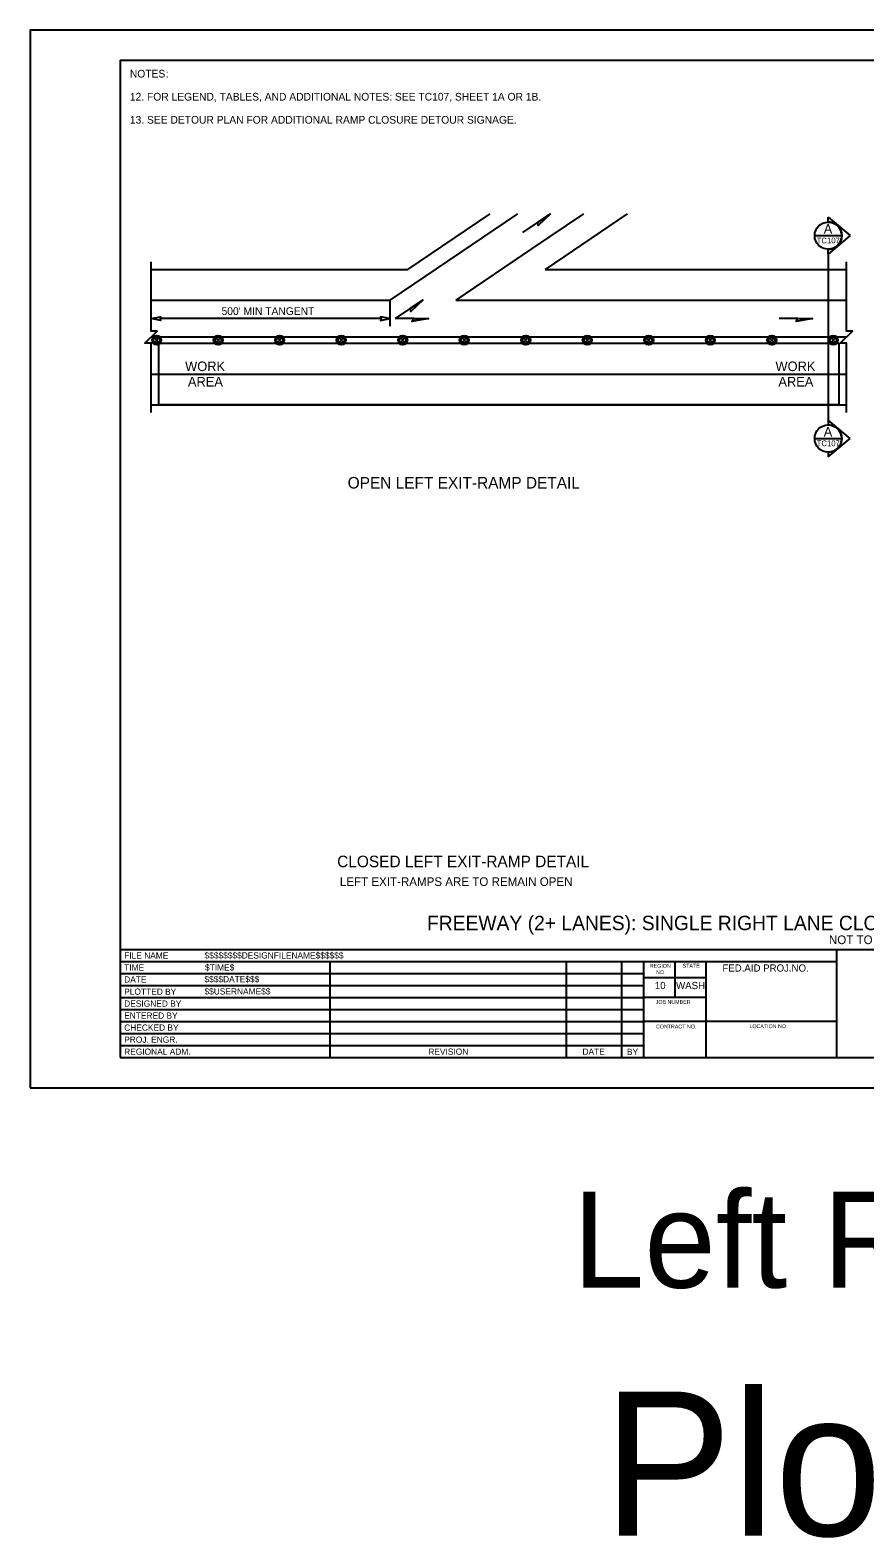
# Model space of a CAD drawing. Extents: x 99999 to 100116, y 99995 to 100013.
# Drawn here: x 100079.06 to 100087.75, y 99995.01 to 100010.69 of the extents above; entities that cross this region are included whole.
import ezdxf

# ---------------------------------------------------------------- set-up
doc = ezdxf.new("R2010")
doc.units = 0
for name, color, linetype in [('RD_MK_LineEdgeYellow', 7, 'Continuous'), ('RD_MK_LineLane', 7, 'Continuous'), ('SH_DE_DetailHeading1Text', 7, 'Continuous'), ('SH_DE_DetailHeading2Text', 7, 'Continuous'), ('SH_GI_GeneralNotesBodyText', 7, 'Continuous'), ('SH_GI_PlotLimits', 7, 'Continuous'), ('SH_GI_SheetBorder', 7, 'Continuous'), ('SH_GI_SheetLocationText', 7, 'Continuous'), ('SH_GI_SheetTextInCells', 7, 'Continuous'), ('SH_GI_TitleBlockText', 7, 'Continuous'), ('SH_TI_WZSectionCut', 7, 'Continuous'), ('TR_WZ_TrafficSafetyDrum', 7, 'Continuous'), ('TR_WZ_WorkAreaLabel', 7, 'Continuous'), ('TR_WZ_WorkZoneDetails', 7, 'Continuous'), ('TR_WZ_WorkZoneTextCurrent', 7, 'Continuous')]:
    doc.layers.add(name, color=color, linetype=linetype)

msp = doc.modelspace()

# ---------------------------------------------------------------- linework, layer by layer
at = {"layer": 'RD_MK_LineEdgeYellow'}
for p, q in [((100084.133, 100008.778), (100082.806, 100007.879)), ((100080.32, 100007.879), (100082.806, 100007.879)), ((100084.421, 100007.879), (100087.555, 100007.879)), ((100080.32, 100007.111), (100087.555, 100007.111))]:
    msp.add_line(p, q, dxfattribs=at)
at = {"layer": 'RD_MK_LineLane'}
msp.add_lwpolyline([(100087.555, 100007.495), (100080.32, 100007.495)], dxfattribs=at)
at = {"layer": 'SH_GI_PlotLimits'}
msp.add_lwpolyline([(100079.062, 99999.687), (100096.062, 99999.687), (100096.062, 100010.687), (100079.062, 100010.687)], close=True, dxfattribs=at)
at = {"layer": 'SH_GI_SheetBorder'}
for p, q in [((100080, 100010.375), (100080, 100000)), ((100080, 100010.375), (100095.75, 100010.375)), ((100080, 100001.126), (100095.75, 100001.126)), ((100087.457, 100000), (100087.457, 100001.126)), ((100080, 100001.001), (100087.457, 100001.001)), ((100082.179, 100001.001), (100082.179, 100000)), ((100084.641, 100001.001), (100084.641, 100000)), ((100085.216, 100001.001), (100085.216, 100000)), ((100085.445, 100001.001), (100085.445, 100000)), ((100085.772, 100000.625), (100085.772, 100001.001)), ((100086.096, 100000), (100086.096, 100001.001)), ((100080, 100000.876), (100082.182, 100000.876)), ((100082.182, 100000.876), (100085.447, 100000.876)), ((100086.096, 100000.831), (100085.447, 100000.831)), ((100080, 100000.751), (100082.182, 100000.751)), ((100080, 100000.625), (100085.447, 100000.625)), ((100082.182, 100000.751), (100085.447, 100000.751)), ((100086.096, 100000.625), (100085.447, 100000.625)), ((100080, 100000.5), (100085.447, 100000.5)), ((100080, 100000.375), (100085.447, 100000.375)), ((100087.457, 100000.375), (100085.447, 100000.375)), ((100080, 100000.25), (100085.447, 100000.25)), ((100080, 100000.125), (100085.447, 100000.125)), ((100080, 100000), (100095.75, 100000))]:
    msp.add_line(p, q, dxfattribs=at)
at = {"layer": 'SH_TI_WZSectionCut'}
for p, q in [((100087.366, 100008.691), (100087.366, 100008.741)), ((100087.366, 100008.741), (100087.594, 100008.55)), ((100087.594, 100008.55), (100087.366, 100008.359)), ((100087.366, 100008.359), (100087.366, 100008.409)), ((100087.366, 100008.359), (100087.366, 100006.631)), ((100087.366, 100006.631), (100087.366, 100006.581)), ((100087.594, 100006.44), (100087.366, 100006.631)), ((100087.366, 100006.249), (100087.594, 100006.44)), ((100087.366, 100006.299), (100087.366, 100006.249))]:
    msp.add_line(p, q, dxfattribs=at)
for points in [[(100087.224, 100008.55), (100087.507, 100008.55)], [(100087.224, 100006.44), (100087.507, 100006.44)]]:
    msp.add_lwpolyline(points, dxfattribs=at)
for centre in [(100087.366, 100008.55), (100087.366, 100006.44)]:
    msp.add_circle(centre, 0.141, dxfattribs=at)
for centre in [(100087.366, 100008.55), (100087.366, 100006.44)]:
    msp.add_arc(centre, 0.141, 269.9978, 90.0022, dxfattribs=at)
at = {"layer": 'TR_WZ_TrafficSafetyDrum'}
for p, q in [((100080.356, 100007.486), (100080.402, 100007.44)), ((100080.402, 100007.486), (100080.356, 100007.44)), ((100080.996, 100007.486), (100081.042, 100007.44)), ((100081.042, 100007.486), (100080.996, 100007.44)), ((100081.636, 100007.486), (100081.682, 100007.44)), ((100081.682, 100007.486), (100081.636, 100007.44)), ((100082.276, 100007.486), (100082.322, 100007.44)), ((100082.322, 100007.486), (100082.276, 100007.44)), ((100082.916, 100007.486), (100082.962, 100007.44)), ((100082.962, 100007.486), (100082.916, 100007.44)), ((100083.556, 100007.486), (100083.602, 100007.44)), ((100083.602, 100007.486), (100083.556, 100007.44)), ((100084.196, 100007.486), (100084.242, 100007.44)), ((100084.242, 100007.486), (100084.196, 100007.44)), ((100084.836, 100007.486), (100084.882, 100007.44)), ((100084.882, 100007.486), (100084.836, 100007.44)), ((100085.476, 100007.486), (100085.522, 100007.44)), ((100085.522, 100007.486), (100085.476, 100007.44)), ((100086.116, 100007.486), (100086.162, 100007.44)), ((100086.162, 100007.486), (100086.116, 100007.44)), ((100086.756, 100007.486), (100086.802, 100007.44)), ((100086.802, 100007.486), (100086.756, 100007.44)), ((100087.396, 100007.486), (100087.442, 100007.44)), ((100087.442, 100007.486), (100087.396, 100007.44))]:
    msp.add_line(p, q, dxfattribs=at)
for centre, radius in [((100080.379, 100007.463), 0.048), ((100080.379, 100007.463), 0.048), ((100080.379, 100007.463), 0.032), ((100081.019, 100007.463), 0.048), ((100081.019, 100007.463), 0.048), ((100081.019, 100007.463), 0.032), ((100081.659, 100007.463), 0.048), ((100081.659, 100007.463), 0.048), ((100081.659, 100007.463), 0.032), ((100082.299, 100007.463), 0.048), ((100082.299, 100007.463), 0.048), ((100082.299, 100007.463), 0.032), ((100082.939, 100007.463), 0.048), ((100082.939, 100007.463), 0.048), ((100082.939, 100007.463), 0.032), ((100083.579, 100007.463), 0.048), ((100083.579, 100007.463), 0.048), ((100083.579, 100007.463), 0.032), ((100084.219, 100007.463), 0.048), ((100084.219, 100007.463), 0.048), ((100084.219, 100007.463), 0.032), ((100084.859, 100007.463), 0.048), ((100084.859, 100007.463), 0.048), ((100084.859, 100007.463), 0.032), ((100085.499, 100007.463), 0.048), ((100085.499, 100007.463), 0.048), ((100085.499, 100007.463), 0.032), ((100086.139, 100007.463), 0.048), ((100086.139, 100007.463), 0.048), ((100086.139, 100007.463), 0.032), ((100086.779, 100007.463), 0.048), ((100086.779, 100007.463), 0.048), ((100086.779, 100007.463), 0.032), ((100087.419, 100007.463), 0.048), ((100087.419, 100007.463), 0.048), ((100087.419, 100007.463), 0.032)]:
    msp.add_circle(centre, radius, dxfattribs=at)
at = {"layer": 'TR_WZ_WorkZoneDetails'}
for p, q in [((100082.993, 100008.199), (100083.848, 100008.778)), ((100084.818, 100008.778), (100084.277, 100008.412)), ((100085.275, 100008.778), (100084.421, 100008.199)), ((100084.345, 100008.69), (100084.186, 100008.582)), ((100084.277, 100008.412), (100083.491, 100007.879)), ((100080.32, 100008.199), (100082.993, 100008.199)), ((100084.421, 100008.199), (100087.555, 100008.199)), ((100082.806, 100007.879), (100082.806, 100007.607)), ((100083.491, 100007.879), (100084.421, 100007.879)), ((100082.713, 100007.687), (100080.414, 100007.687)), ((100083.02, 100007.795), (100082.86, 100007.687)), ((100083.053, 100007.687), (100082.86, 100007.687)), ((100087.049, 100007.687), (100086.856, 100007.687)), ((100080.32, 100006.791), (100087.555, 100006.791))]:
    msp.add_line(p, q, dxfattribs=at)
for points in [[(100084.476, 100008.778), (100084.348, 100008.655), (100084.345, 100008.69)], [(100083.15, 100007.883), (100083.022, 100007.76), (100083.02, 100007.795)], [(100080.32, 100007.687), (100080.418, 100007.706), (100080.414, 100007.687), (100080.418, 100007.668)], [(100082.806, 100007.687), (100082.708, 100007.706), (100082.713, 100007.687), (100082.708, 100007.668)], [(100083.21, 100007.687), (100083.035, 100007.656), (100083.053, 100007.687)], [(100087.206, 100007.687), (100087.031, 100007.656), (100087.049, 100007.687)], [(100080.4, 100006.791), (100080.4, 100007.431), (100087.475, 100007.431), (100087.475, 100006.791)]]:
    msp.add_lwpolyline(points, close=True, dxfattribs=at)
for points in [[(100080.32, 100006.711), (100080.32, 100007.433), (100080.256, 100007.433), (100080.384, 100007.557), (100080.32, 100007.557), (100080.32, 100008.279)], [(100087.555, 100006.711), (100087.555, 100007.433), (100087.491, 100007.433), (100087.619, 100007.557), (100087.555, 100007.557), (100087.555, 100008.279)]]:
    msp.add_lwpolyline(points, dxfattribs=at)

# ---------------------------------------------------------------- texts
at = {"layer": 'SH_DE_DetailHeading1Text'}
for s, height, p in [('FREEWAY (2+ LANES): SINGLE RIGHT LANE CLOSURE (MAINTAIN EXISTING SPEED LIMIT)', 0.15, (100083.191, 100001.326)), ('NOT TO SCALE', 0.09, (100087.373, 100001.181))]:
    msp.add_text(s, height=height, rotation=360, dxfattribs=at).set_placement(p)
at = {"layer": 'SH_DE_DetailHeading2Text'}
for s, height, p in [('OPEN LEFT EXIT-RAMP DETAIL', 0.12, (100082.366, 100005.92)), ('CLOSED LEFT EXIT-RAMP DETAIL', 0.12, (100082.257, 100001.981)), ('LEFT EXIT-RAMPS ARE TO REMAIN OPEN', 0.09, (100082.285, 100001.786))]:
    msp.add_text(s, height=height, rotation=360, dxfattribs=at).set_placement(p)
at = {"layer": 'SH_GI_GeneralNotesBodyText'}
for s, p in [('NOTES', (100080.1, 100010.195)), (':', (100080.474, 100010.195)), ('12. FOR LEGEND, TABLES, AND ADDITIONAL NOTES: SEE TC107, SHEET 1A OR 1B.', (100080.1, 100009.955)), ('13. SEE DETOUR PLAN FOR ADDITIONAL RAMP CLOSURE DETOUR SIGNAGE.', (100080.1, 100009.715))]:
    msp.add_text(s, height=0.08, rotation=360, dxfattribs=at).set_placement(p)
at = {"layer": 'SH_GI_SheetLocationText'}
for s, height, p in [('Left Ramps', 1, (100084.709, 99997.607)), ('Plot 5', 1.5, (100085.026, 99995.027))]:
    msp.add_text(s, height=height, dxfattribs=at).set_placement(p)
at = {"layer": 'SH_GI_SheetTextInCells'}
for s, height, p in [('FILE NAME', 0.0651, (100080.041, 100001.031)), ('TIME', 0.0651, (100080.041, 100000.906)), ('REGION', 0.04, (100085.51, 100000.935)), ('STATE', 0.04, (100085.851, 100000.936)), ('FED.AID PROJ.NO.', 0.07506, (100086.265, 100000.895)), ('DATE', 0.0651, (100080.041, 100000.781)), ('10', 0.0751, (100085.562, 100000.713)), ('NO.', 0.04, (100085.575, 100000.869)), ('WASH', 0.0751, (100085.783, 100000.713)), ('PLOTTED BY', 0.0651, (100080.041, 100000.654)), ('DESIGNED BY', 0.06505, (100080.041, 100000.53)), ('ENTERED BY', 0.0651, (100080.041, 100000.405)), ('JOB NUMBER', 0.04, (100085.571, 100000.559)), ('CHECKED BY', 0.0651, (100080.041, 100000.28)), ('CONTRACT NO.', 0.04003, (100085.573, 100000.304)), ('LOCATION NO.', 0.04003, (100086.546, 100000.307)), ('PROJ. ENGR.', 0.06505, (100080.041, 100000.155)), ('REGIONAL ADM.', 0.06505, (100080.041, 100000.03)), ('REVISION', 0.0651, (100083.205, 100000.03)), ('DATE', 0.0651, (100084.809, 100000.03)), ('BY', 0.0651, (100085.272, 100000.028))]:
    msp.add_text(s, height=height, dxfattribs=at).set_placement(p)
at = {"layer": 'SH_GI_TitleBlockText'}
for s, height, p in [('$$$$$$$$DESIGNFILENAME$$$$$$', 0.06505, (100080.877, 100001.031)), ('$TIME$', 0.0651, (100080.882, 100000.906)), ('$$$$DATE$$$', 0.06505, (100080.876, 100000.784)), ('$$USERNAME$$', 0.06505, (100080.876, 100000.657))]:
    msp.add_text(s, height=height, dxfattribs=at).set_placement(p)
at = {"layer": 'SH_TI_WZSectionCut'}
for s, height, rotation, p in [('A', 0.1, 0.01, (100087.319, 100008.571)), ('TC107', 0.06, 360, (100087.246, 100008.47)), ('A', 0.1, 0.01, (100087.319, 100006.46)), ('TC107', 0.06, 360, (100087.246, 100006.36))]:
    msp.add_text(s, height=height, rotation=rotation, dxfattribs=at).set_placement(p)
at = {"layer": 'TR_WZ_WorkAreaLabel'}
for s, p in [('WORK', (100080.675, 100007.141)), ('WORK', (100086.817, 100007.141)), ('AREA', (100080.704, 100006.981)), ('AREA', (100086.847, 100006.981))]:
    msp.add_text(s, height=0.1, dxfattribs=at).set_placement(p)
at = {"layer": 'TR_WZ_WorkZoneTextCurrent'}
msp.add_text("500' MIN TANGENT", height=0.08, dxfattribs=at).set_placement((100081.054, 100007.725))

doc.saveas('drawing.dxf')
